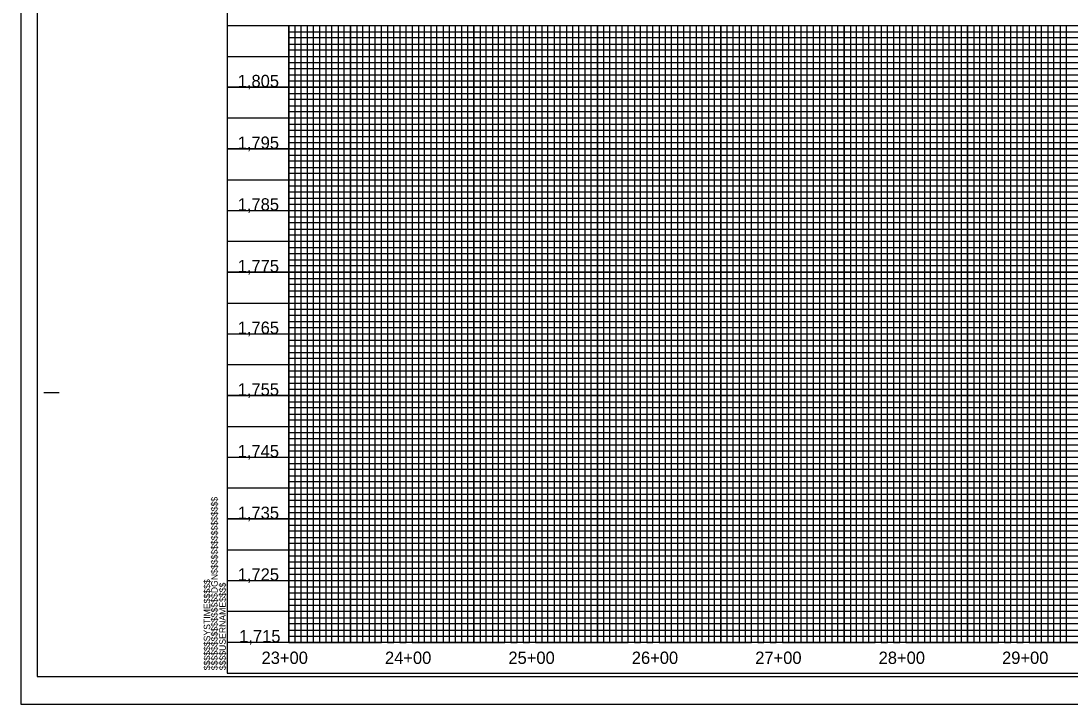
# Model space of a CAD drawing. Extents: x 505692 to 507376, y 438761 to 439861.
# Drawn here: x 505692 to 506542, y 438761 to 439315 of the extents above; entities that cross this region are included whole.
import ezdxf

# ---------------------------------------------------------------- set-up
doc = ezdxf.new("R2010")
doc.units = 0
for name, color, linetype in [('Exist Vertical Profile Vertical Axis Label', 7, 'Continuous'), ('Sheet Cutting Line CELL', 7, 'Continuous'), ('Sheet DOT Grid CELL', 7, 'Continuous'), ('Sheet Layout Profile Border Port 2', 7, 'Continuous'), ('Sheet Plot Border Inside CELL', 7, 'Continuous'), ('Sheet Plot Border Outside CELL', 7, 'Continuous'), ('Sheet Profile CELL', 7, 'Continuous'), ('Sheet Profile Grid Major CELL', 7, 'Continuous'), ('Sheet Profile Grid Middle CELL', 7, 'Continuous'), ('Sheet Profile Grid Minor CELL', 7, 'Continuous')]:
    doc.layers.add(name, color=color, linetype=linetype)

msp = doc.modelspace()

# ---------------------------------------------------------------- linework, layer by layer
at = {"layer": 'Sheet Cutting Line CELL'}
msp.add_line((505691.68, 439861.14), (505691.68, 438761.14), dxfattribs=at)
at = {"layer": 'Sheet DOT Grid CELL'}
for p, q in [((505858.68, 439311.14), (507358.56, 439311.14)), ((505908.68, 439311.14), (505908.68, 438811.14)), ((505958.68, 439311.14), (505958.68, 438811.14)), ((506008.68, 439311.14), (506008.68, 438811.14)), ((506058.68, 439311.14), (506058.68, 438811.14)), ((506108.68, 439311.14), (506108.68, 438811.14)), ((506158.68, 439311.14), (506158.68, 438811.14)), ((506208.68, 439311.14), (506208.68, 438811.14)), ((506258.68, 439311.14), (506258.68, 438811.14)), ((506308.68, 439311.14), (506308.68, 438811.14)), ((506358.68, 439311.14), (506358.68, 438811.14)), ((506408.68, 439311.14), (506408.68, 438811.14)), ((506458.68, 439311.14), (506458.68, 438811.14)), ((506508.68, 439311.14), (506508.68, 438811.14)), ((505858.68, 439261.14), (507358.56, 439261.14)), ((505858.68, 439211.14), (507358.56, 439211.14)), ((505858.68, 439161.14), (507358.56, 439161.14)), ((505858.68, 439111.14), (507358.56, 439111.14)), ((505858.68, 439061.14), (507358.56, 439061.14)), ((505858.68, 439011.14), (507358.56, 439011.14)), ((505858.68, 438961.14), (507358.56, 438961.14)), ((505858.68, 438911.14), (507358.56, 438911.14)), ((505858.68, 438861.14), (507358.56, 438861.14))]:
    msp.add_line(p, q, dxfattribs=at)
at = {"layer": 'Sheet Layout Profile Border Port 2'}
msp.add_lwpolyline([(505908.72, 439311.14), (507308.72, 439311.14), (507308.72, 438811.14), (505908.72, 438811.14)], close=True, dxfattribs=at)
at = {"layer": 'Sheet Plot Border Inside CELL'}
msp.add_lwpolyline([(505704.68, 438783.59), (507371.18, 438783.59), (507371.18, 439838.69), (505704.68, 439838.69)], close=True, dxfattribs=at)
at = {"layer": 'Sheet Plot Border Outside CELL'}
msp.add_lwpolyline([(505691.68, 438761.14), (507375.68, 438761.14), (507375.68, 439861.14), (505691.68, 439861.14)], close=True, dxfattribs=at)
at = {"layer": 'Sheet Profile CELL'}
for p, q in [((505858.68, 439311.14), (507358.68, 439311.14)), ((505710.18, 439013.64), (505722.68, 439013.64)), ((507358.68, 438811.14), (505858.68, 438811.14)), ((505858.68, 438786.14), (507358.68, 438786.14)), ((505858.68, 438786.14), (505858.68, 438786.14)), ((505858.68, 438786.14), (505858.68, 438786.14)), ((505858.68, 438786.14), (505858.68, 438786.14)), ((505858.68, 438786.14), (505858.68, 438786.14)), ((505858.68, 438786.14), (505858.68, 438786.14)), ((505858.68, 438786.14), (505858.68, 438786.14)), ((505858.68, 438786.14), (505858.68, 438786.14))]:
    msp.add_line(p, q, dxfattribs=at)
msp.add_lwpolyline([(507358.68, 439836.14), (505858.68, 439836.14), (505858.68, 438786.14), (507358.68, 438786.14)], close=True, dxfattribs=at)
msp.add_lwpolyline([(505896.18, 438786.14), (505896.18, 438786.14)], dxfattribs=at)
at = {"layer": 'Sheet Profile Grid Major CELL'}
for p, q in [((506358.68, 439311.14), (506408.68, 439311.14)), ((506358.68, 439311.14), (506408.68, 439311.14)), ((506458.68, 439311.14), (506508.68, 439311.14)), ((506458.68, 439311.14), (506508.68, 439311.14)), ((505858.68, 438811.14), (505858.68, 438811.14))]:
    msp.add_line(p, q, dxfattribs=at)
for points in [[(505908.68, 439311.14), (505908.68, 438811.14), (505958.68, 438811.14), (505958.68, 439311.14), (506008.68, 439311.14), (506008.68, 438811.14), (506058.68, 438811.14), (506058.68, 439311.14), (506108.68, 439311.14), (506108.68, 438811.14), (506158.68, 438811.14), (506158.68, 439311.14), (506208.68, 439311.14), (506208.68, 438811.14), (506258.68, 438811.14), (506258.68, 439311.14), (506308.68, 439311.14), (506308.68, 438811.14), (506358.68, 438811.14), (506358.68, 439311.14), (506408.68, 439311.14), (506408.68, 438811.14), (506458.68, 438811.14), (506458.68, 439311.14), (506508.68, 439311.14), (506508.68, 438811.14), (506558.68, 438811.14)], [(507358.68, 439261.14), (505858.68, 439261.14)], [(507358.68, 439211.14), (505858.68, 439211.14), (505858.68, 439161.14), (507358.68, 439161.14)], [(507358.68, 439111.14), (505858.68, 439111.14), (505858.68, 439061.14), (507358.68, 439061.14)], [(507358.68, 439011.14), (505858.68, 439011.14), (505858.68, 438961.14), (507358.68, 438961.14)], [(507358.68, 438911.14), (505858.68, 438911.14), (505858.68, 438911.14), (505858.68, 438861.14), (507358.68, 438861.14)], [(507358.68, 438811.14), (505858.68, 438811.14)]]:
    msp.add_lwpolyline(points, dxfattribs=at)
at = {"layer": 'Sheet Profile Grid Middle CELL'}
for points in [[(505883.68, 439311.14), (505933.68, 439311.14), (505933.68, 438811.14), (505983.68, 438811.14), (505983.68, 439311.14), (506033.68, 439311.14), (506033.68, 438811.14), (506083.68, 438811.14), (506083.68, 439311.14), (506133.68, 439311.14), (506133.68, 438811.14), (506183.68, 438811.14), (506183.68, 439311.14), (506233.68, 439311.14), (506233.68, 438811.14), (506283.68, 438811.14), (506283.68, 439311.14), (506333.68, 439311.14), (506333.68, 438811.14), (506383.68, 438811.14), (506383.68, 439311.14), (506433.68, 439311.14), (506433.68, 438811.14), (506483.68, 438811.14), (506483.68, 438811.14), (506483.68, 439311.14), (506533.68, 439311.14), (506533.68, 438811.14), (506583.68, 438811.14)], [(505858.68, 439286.14), (507358.68, 439286.14)], [(507358.68, 439236.14), (505858.68, 439236.14), (505858.68, 439186.14), (507358.68, 439186.14)], [(507358.68, 439136.14), (505858.68, 439136.14), (505858.68, 439086.14), (507358.68, 439086.14)], [(507358.68, 439036.14), (505858.68, 439036.14), (505858.68, 438986.14), (507358.68, 438986.14)], [(507358.68, 438936.14), (505858.68, 438936.14), (505858.68, 438886.14), (507358.68, 438886.14)], [(507358.68, 438836.14), (505858.68, 438836.14)]]:
    msp.add_lwpolyline(points, dxfattribs=at)
at = {"layer": 'Sheet Profile Grid Minor CELL'}
for p, q in [((505908.68, 439306.14), (507308.68, 439306.14)), ((507308.68, 439301.14), (505908.68, 439301.14)), ((505908.68, 439296.14), (507308.68, 439296.14)), ((507308.68, 439291.14), (505908.68, 439291.14)), ((505908.68, 439281.14), (507308.68, 439281.14)), ((507308.68, 439276.14), (505908.68, 439276.14)), ((505908.68, 439271.14), (507308.68, 439271.14)), ((507308.68, 439266.14), (505908.68, 439266.14)), ((505908.68, 439256.14), (507308.68, 439256.14)), ((507308.68, 439251.14), (505908.68, 439251.14)), ((505908.68, 439246.14), (507308.68, 439246.14)), ((507308.68, 439241.14), (505908.68, 439241.14)), ((505908.68, 439231.14), (507308.68, 439231.14)), ((507308.68, 439226.14), (505908.68, 439226.14)), ((505908.68, 439221.14), (507308.68, 439221.14)), ((507308.68, 439216.14), (505908.68, 439216.14)), ((505908.68, 439206.14), (507308.68, 439206.14)), ((507308.68, 439201.14), (505908.68, 439201.14)), ((505908.68, 439196.14), (507308.68, 439196.14)), ((507308.68, 439191.14), (505908.68, 439191.14)), ((505908.68, 439181.14), (507308.68, 439181.14)), ((507308.68, 439176.14), (505908.68, 439176.14)), ((505908.68, 439171.14), (507308.68, 439171.14)), ((507308.68, 439166.14), (505908.68, 439166.14)), ((505908.68, 439156.14), (507308.68, 439156.14)), ((507308.68, 439151.14), (505908.68, 439151.14)), ((505908.68, 439146.14), (507308.68, 439146.14)), ((507308.68, 439141.14), (505908.68, 439141.14)), ((505908.68, 439131.14), (507308.68, 439131.14)), ((507308.68, 439126.14), (505908.68, 439126.14)), ((505908.68, 439121.14), (507308.68, 439121.14)), ((507308.68, 439116.14), (505908.68, 439116.29)), ((505908.68, 439106.14), (507308.68, 439106.14)), ((507308.68, 439101.14), (505908.68, 439101.14)), ((505908.68, 439096.14), (507308.68, 439096.14)), ((507308.68, 439091.14), (505908.68, 439091.14)), ((505908.68, 439081.14), (507308.68, 439081.14)), ((507308.68, 439076.14), (505908.68, 439076.14)), ((505908.68, 439071.14), (507308.68, 439071.14)), ((507308.68, 439066.14), (505908.68, 439066.14)), ((505908.68, 439056.14), (507308.68, 439056.14)), ((507308.68, 439051.14), (505908.68, 439051.14)), ((505908.68, 439046.14), (507308.68, 439046.14)), ((507308.68, 439041.14), (505908.68, 439041.14)), ((505908.68, 439031.14), (507308.68, 439031.14)), ((507308.68, 439026.14), (505908.68, 439026.14)), ((505908.68, 439021.14), (507308.68, 439021.14)), ((507308.68, 439016.14), (505908.68, 439016.14)), ((505908.68, 439006.14), (507308.68, 439006.14)), ((507308.68, 439001.14), (505908.68, 439001.14)), ((505908.68, 438996.14), (507308.68, 438996.14)), ((507308.68, 438991.14), (505908.68, 438991.14)), ((505908.68, 438981.14), (507308.68, 438981.14)), ((507308.68, 438976.14), (505908.68, 438976.14)), ((505908.68, 438971.14), (507308.68, 438971.14)), ((507308.68, 438966.14), (505908.68, 438966.14)), ((505908.68, 438956.14), (507308.68, 438956.14)), ((507308.68, 438951.14), (505908.68, 438951.14)), ((505908.68, 438946.14), (507308.68, 438946.14)), ((507308.68, 438941.14), (505908.68, 438941.14)), ((505908.68, 438931.14), (507308.68, 438931.14)), ((507308.68, 438926.14), (505908.68, 438926.14)), ((505908.68, 438921.14), (507308.68, 438921.14)), ((507308.68, 438916.14), (505908.68, 438916.14)), ((505908.68, 438906.14), (507308.68, 438906.14)), ((507308.68, 438901.14), (505908.68, 438901.14)), ((505908.68, 438896.14), (507308.68, 438896.14)), ((507308.68, 438891.14), (505908.68, 438891.14)), ((505908.68, 438881.14), (507308.68, 438881.14)), ((507308.68, 438876.14), (505908.68, 438876.14)), ((505908.68, 438871.14), (507308.68, 438871.14)), ((507308.68, 438866.14), (505908.68, 438866.14)), ((505908.68, 438856.14), (507308.68, 438856.14)), ((507308.68, 438851.14), (505908.68, 438851.14)), ((505908.68, 438846.14), (507308.68, 438846.14)), ((507308.68, 438841.14), (505908.68, 438841.14)), ((505908.68, 438831.14), (507308.68, 438831.14)), ((507308.68, 438826.14), (505908.68, 438826.14)), ((505908.68, 438821.14), (507308.68, 438821.14)), ((505908.68, 438816.14), (507308.68, 438816.14))]:
    msp.add_line(p, q, dxfattribs=at)
for points in [[(505908.68, 439311.14), (505913.68, 439311.14), (505913.68, 438811.14), (505918.68, 438811.14), (505918.68, 439311.14), (505923.68, 439311.14), (505923.68, 438811.14), (505928.68, 438811.14), (505928.68, 439311.14), (505938.68, 439311.14), (505938.68, 438811.14), (505943.68, 438811.14), (505943.68, 439311.14), (505948.68, 439311.14), (505948.68, 438811.14), (505953.68, 438811.14), (505963.68, 438811.14), (505968.68, 438811.14), (505968.68, 439311.14), (505973.68, 439311.14), (505973.68, 438811.14), (505978.68, 438811.14), (505978.68, 439311.14), (505988.68, 439311.14), (505988.68, 438811.14), (505993.68, 438811.14), (505993.68, 439311.14), (505998.68, 439311.14), (505998.68, 438811.14), (506003.68, 438811.14), (506003.68, 439311.14), (506013.68, 439311.14), (506013.68, 438811.14), (506018.68, 438811.14), (506018.68, 439311.14), (506023.68, 439311.14), (506023.68, 438811.14), (506028.68, 438811.14), (506028.68, 439311.14), (506038.68, 439311.14), (506038.68, 438811.14), (506043.68, 438811.14), (506043.68, 439311.14), (506048.68, 439311.14), (506048.68, 438811.14), (506053.68, 438811.14), (506053.68, 439311.14), (506063.68, 439311.14), (506063.68, 438811.14), (506068.68, 438811.14), (506068.68, 439311.14), (506073.68, 439311.14), (506073.68, 438811.14), (506078.68, 438811.14), (506078.68, 439311.14), (506088.68, 439311.14), (506088.68, 438811.14), (506093.68, 438811.14), (506093.68, 439311.14), (506098.68, 439311.14), (506098.68, 438811.14), (506103.68, 438811.14), (506103.68, 439311.14), (506113.68, 439311.14), (506113.68, 438811.14), (506118.68, 438811.14), (506118.68, 439311.14), (506123.68, 439311.14), (506123.68, 438811.14)], [(505953.68, 438811.14), (505953.68, 439311.14), (505963.68, 439311.14), (505963.68, 438811.14)], [(506123.68, 438811.14), (506128.68, 438811.14), (506128.68, 439311.14), (506138.68, 439311.14), (506138.68, 438811.14), (506143.68, 438811.14), (506143.68, 439311.14), (506148.68, 439311.14), (506148.68, 438811.14), (506153.68, 438811.14), (506153.68, 439311.14), (506163.68, 439311.14), (506163.68, 438811.14), (506168.68, 438811.14), (506168.68, 439311.14), (506173.68, 439311.14), (506173.68, 438811.14), (506178.68, 438811.14), (506178.68, 439311.14), (506188.68, 439311.14), (506188.68, 438811.14), (506193.68, 438811.14), (506193.68, 439311.14), (506198.68, 439311.14), (506198.68, 438811.14), (506203.68, 438811.14), (506203.68, 439311.14), (506213.68, 439311.14), (506213.68, 438811.14), (506218.68, 438811.14), (506218.68, 439311.14), (506223.68, 439311.14), (506223.68, 438811.14), (506228.68, 438811.14), (506228.68, 439311.14), (506238.68, 439311.14), (506238.68, 438811.14), (506243.68, 438811.14), (506243.68, 439311.14), (506248.68, 439311.14), (506248.68, 438811.14), (506253.68, 438811.14), (506253.68, 439311.14), (506263.68, 439311.14), (506263.68, 438811.14), (506268.68, 438811.14), (506268.68, 439311.14), (506273.68, 439311.14), (506273.68, 438811.14), (506278.68, 438811.14), (506278.68, 439311.14), (506288.68, 439311.14), (506288.68, 438811.14), (506293.68, 438811.14), (506293.68, 439311.14), (506298.68, 439311.14), (506298.68, 438811.14), (506303.68, 438811.14), (506303.68, 439311.14), (506313.68, 439311.14), (506313.68, 438811.14), (506318.68, 438811.14), (506318.68, 439311.14), (506323.68, 439311.14), (506323.68, 438811.14), (506328.68, 438811.14), (506328.68, 439311.14), (506338.68, 439311.14), (506338.68, 438811.14), (506343.68, 438811.14), (506343.68, 439311.14), (506348.68, 439311.14), (506348.68, 438811.14), (506353.68, 438811.14), (506353.68, 439311.14), (506363.68, 439311.14), (506363.68, 438811.14), (506368.68, 438811.14), (506368.68, 439311.14), (506373.68, 439311.14), (506373.68, 438811.14), (506378.68, 438811.14), (506378.68, 439311.14), (506388.68, 439311.14), (506388.68, 438811.14), (506393.68, 438811.14), (506393.68, 439311.14), (506398.68, 439311.14), (506398.68, 438811.14), (506403.68, 438811.14), (506403.68, 439311.14), (506413.68, 439311.14), (506413.68, 438811.14), (506418.68, 438811.14), (506418.68, 439311.14), (506423.68, 439311.14), (506423.68, 438811.14), (506428.68, 438811.14), (506428.68, 439311.14), (506438.68, 439311.14)], [(506438.68, 439311.14), (506438.68, 438811.14), (506443.68, 438811.14), (506443.68, 439311.14), (506448.68, 439311.14), (506448.68, 438811.14), (506453.68, 438811.14), (506453.68, 439311.14), (506463.68, 439311.14), (506463.68, 438811.14), (506468.68, 438811.14), (506468.68, 439311.14), (506473.68, 439311.14), (506473.68, 438811.14), (506478.68, 438811.14), (506478.68, 439311.14), (506488.68, 439311.14), (506488.68, 438811.14), (506493.68, 438811.14), (506493.68, 439311.14), (506498.68, 439311.14), (506498.68, 438811.14), (506503.68, 438811.14), (506503.68, 439311.14), (506513.68, 439311.14), (506513.68, 438811.14), (506518.68, 438811.14), (506518.68, 439311.14), (506523.68, 439311.14), (506523.68, 438811.14), (506528.68, 438811.14), (506528.68, 439311.14), (506538.68, 439311.14), (506538.68, 438811.14), (506543.68, 438811.14)]]:
    msp.add_lwpolyline(points, dxfattribs=at)

# ---------------------------------------------------------------- texts
at = {"layer": 'Exist Vertical Profile Vertical Axis Label'}
for s, p in [('1,805', (505867.29, 439261.14)), ('1,795', (505867.29, 439211.14)), ('1,785', (505867.29, 439161.14)), ('1,775', (505867.29, 439111.14)), ('1,765', (505867.29, 439061.14)), ('1,755', (505867.29, 439011.14)), ('1,745', (505867.29, 438961.14)), ('1,735', (505867.29, 438911.14)), ('1,725', (505867.29, 438861.14)), ('1,715', (505868.49, 438811.14)), ('23+00', (505886.61, 438793.64)), ('24+00', (505986.61, 438793.64)), ('25+00', (506086.61, 438793.64)), ('26+00', (506186.61, 438793.64)), ('27+00', (506286.61, 438793.64)), ('28+00', (506386.61, 438793.64)), ('29+00', (506486.61, 438793.64))]:
    msp.add_text(s, height=10, dxfattribs=at).set_placement(p)
at = {"layer": 'Sheet Profile CELL'}
for s, p in [('$$$$$$$$$$$$$$$$DGN$$$$$$$$$$$$$$$$', (505851.04, 438788.52)), ('$$$$$$SYSTIME$$$$$', (505844.99, 438788.52)), ('$$$$USERNAME$$$$', (505857.62, 438788.53))]:
    msp.add_text(s, height=5.25, rotation=90, dxfattribs=at).set_placement(p)

doc.saveas('drawing.dxf')
